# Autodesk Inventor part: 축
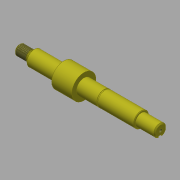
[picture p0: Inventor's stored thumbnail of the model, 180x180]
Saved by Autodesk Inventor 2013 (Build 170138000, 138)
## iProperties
Created: 2016-08
Part Number: 축
Material: 강철, 탄소
Document SubType Name: Modeling
Designer: mduedu
Density: 7.87 g/cm^3
Author: mduedu
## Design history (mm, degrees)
sketch "스케치1"
  geometry: L1 (-70, 0)-(70, 0); L2 (-70, 0)-(-70, 5); L3 (-70, 5)-(-56, 5); L4 (-56, 5)-(-56, 7.5); L5 (-56, 7.5)-(51, 7.5); L6 (51, 7.5)-(51, 6); L7 (51, 6)-(70, 6); L8 (70, 6)-(70, 0); 2 further points
  constraints: 16 end point, 5 parallel, 2 perpendicular, 1 coincident, 1 horizontal, 1 midpoint
  dimensions: "d0" = 140 distance of L1.start L1.end; "d2" = 14 distance of L2.end L3.end; "d3" = 19 distance of L6.end L7.end; "d4" = 10 diameter of L3 L1; "d5" = 15 diameter of L5 L1; "d6" = 12 diameter of L7 L1
revolve "회전1" sketch "스케치1" stored, may be unused: angle "d7" = 90 deg
sketch "스케치2"
  geometry: L1 (-56, -5)-(-56, 5) reference; L2 (70, -6)-(70, 6) reference; L3 (-56, 0)-(70, 0); L4 (-58, 4.5)-(-58, 5); L5 (-58, 5)-(-56, 5); L6 (-56, 5)-(-56, 4.5); L7 (-58, 4.5)-(-56, 4.5); 1 further point
  constraints: 10 end point, 2 midpoint, 1 parallel, 1 perpendicular, 1 point on line
  dimensions: "d8" = 2 distance of L4.end L5.end; "d10" = 10 diameter of L5 L3; "d11" = 9 diameter of L7 L3
revolve "회전2" sketch "스케치2" stored, may be unused: angle "d12" = 90 deg
node "작업 평면1"
sketch "스케치3"
  geometry: C1 r 12 at (0, 0); 1 further point
  constraints: 1 centre point, 1 coincident
  dimensions: "d15" = 24 diameter of C1
extrude "돌출1" join sketch "스케치3" distance "d16" = 20; taper "d17" = 0 deg
sketch "스케치5"
  geometry: L1 (-70, -5)-(-70, 5) reference; L2 (70, -6)-(70, 6) reference; L3 (-70, 0)-(70, 0); L4 (-6, 7.5)-(51, 7.5) reference; L5 (15.15, 7.5)-(14, 7.5); L6 (14, 7.5)-(14, 7.15); L7 (14, 7.15)-(15.15, 7.15); L8 (15.15, 7.15)-(15.15, 7.5); 1 further point
  constraints: 10 end point, 2 midpoint, 2 parallel, 1 horizontal, 1 perpendicular, 1 point on line
  dimensions: "d19" = 56 distance between parallel lines of L6 L2; "d20" = 1.15 distance between parallel lines of L8 L6; "d21" = 14.3 diameter of L7 L3
revolve "회전3" sketch "스케치5" stored, may be unused: angle "d22" = 90 deg
node "작업 평면3"
sketch "스케치6"
  geometry: L1 (9.5, 7.5)-(9.5, -7.5) reference; L2 (7.5, 2)-(-9.5, 2); L3 (-9.5, 2)-(-9.5, -2); L4 (-9.5, -2)-(7.5, -2); L5 (-9.5, 6)-(-9.5, -6) reference; A1 r 2 centre (7.5, 0) between (7.5, -2) and (7.5, 2); 2 further points
  constraints: 6 end point, 3 tangent, 2 midpoint, 2 point on circle, 1 centre point, 1 horizontal, 1 horizontal alignment, 1 parallel, 1 perpendicular
  dimensions: "d23" = 4 distance between parallel lines of L4 L2
extrude "돌출2" cut sketch "스케치6" distance "d25" = 2.5; taper "d26" = 0 deg
feature "스레드1" dims "d27" = 10, "d28" = 0
chamfer "모따기5" distance "d41" = 0.5; stored, may be unused: second distance "d42" = 2, angle "d43" = 45 deg
chamfer "모따기6" distance "d44" = 0.5; stored, may be unused: second distance "d45" = 2, angle "d46" = 45 deg
chamfer "모따기7" distance "d47" = 1; stored, may be unused: second distance "d48" = 2, angle "d49" = 45 deg
chamfer "모따기8" distance "d50" = 1; stored, may be unused: second distance "d51" = 2, angle "d52" = 45 deg
sketch "스케치8"
  geometry: 1 further point
hole "구멍1" sketch "스케치8" at (2, 3.5) diameter "d53" = 3.242; stored, may be unused: countersink angle "d57" = 90 deg, drill point angle "d59" = 120 deg; dims "d54" = 10, "d55" = 4, "d56" = 2, "d58" = 12
node "솔리드1"
other parameters: "d13" = -44
